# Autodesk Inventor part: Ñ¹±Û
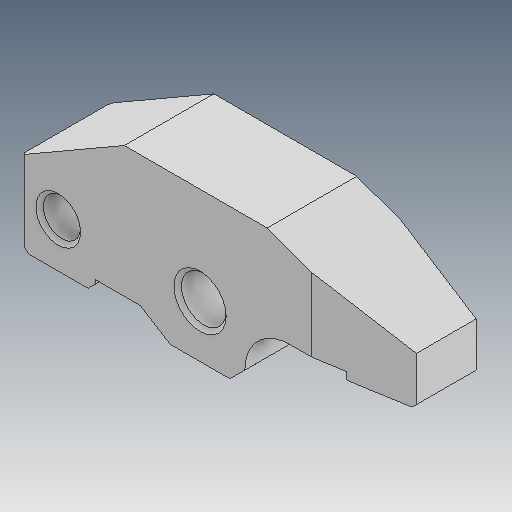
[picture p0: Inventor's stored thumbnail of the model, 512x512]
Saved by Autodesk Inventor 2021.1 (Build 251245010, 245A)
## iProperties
Created: 2015-08
Part Number: Ñ¹±Û
Material: Ogólny
Document SubType Name: Modeling
Designer: user
Density: 1 g/cm^3
Appearance: Domyślna
Author: user
Revision Number: ÈÎºÎ
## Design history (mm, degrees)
feature "µ¹½Ç2"
node "Bryła1"
